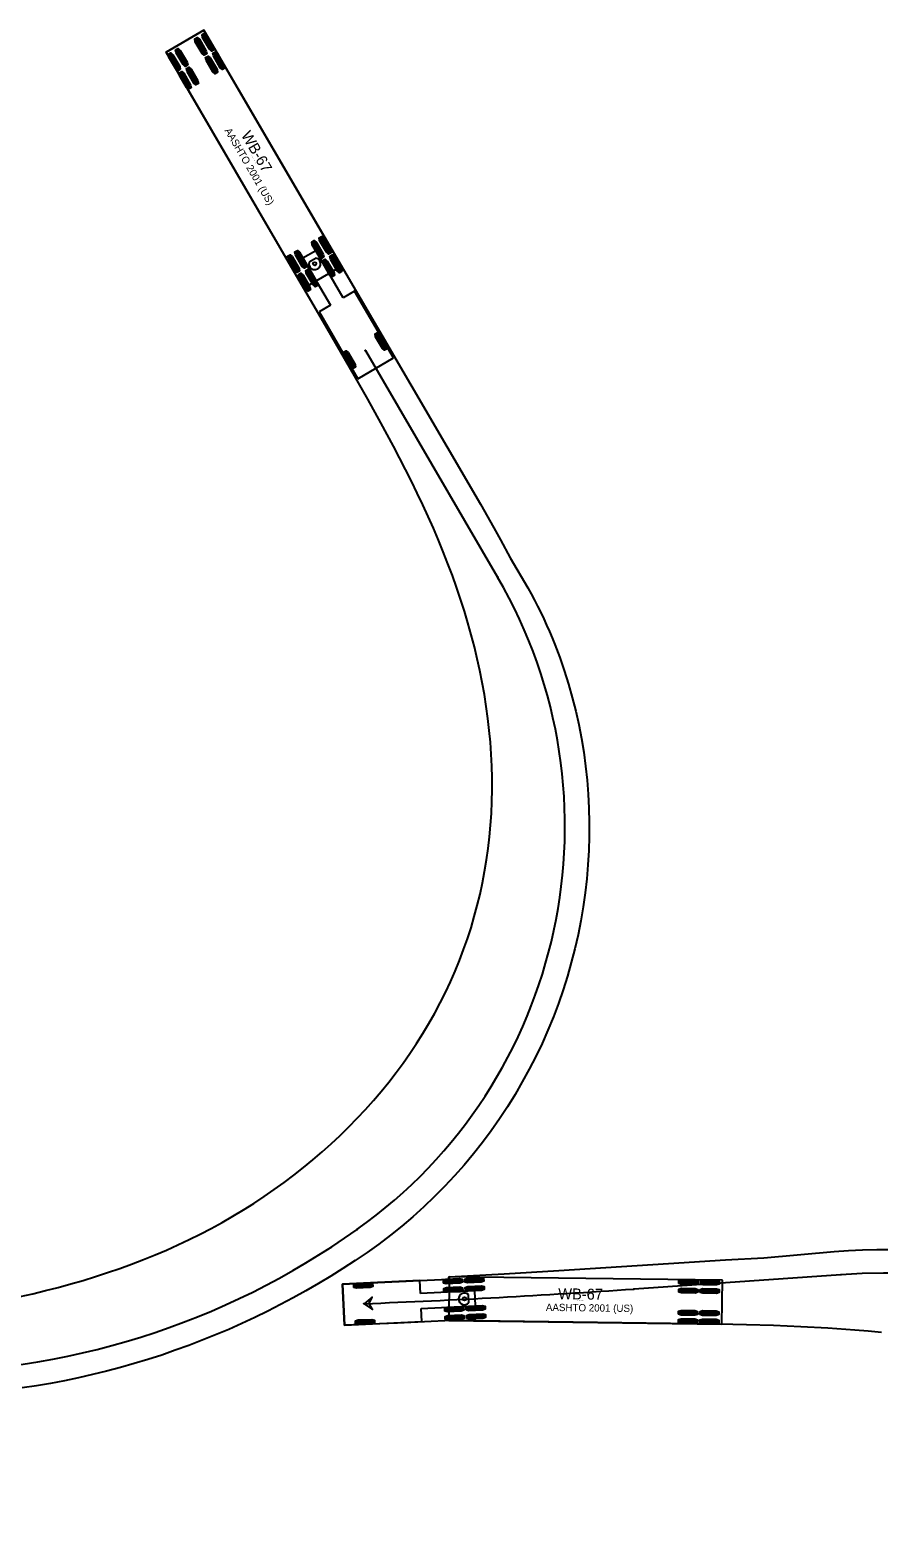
# Model space of a CAD drawing. Extents: x 1639988 to 1641860, y 841974 to 844187.
# Drawn here: x 1640795.3 to 1640960, y 842634.4 to 842927 of the extents above; entities that cross this region are included whole.
import ezdxf

# ---------------------------------------------------------------- set-up
doc = ezdxf.new("R2010")
doc.units = 0
doc.layers.add('Scratch_Level_1', color=7, linetype='Continuous')

msp = doc.modelspace()

# ---------------------------------------------------------------- linework, layer by layer
at = {"layer": 'Scratch_Level_1'}
for p, q in [((1640829.03, 842926.97), (1640821.69, 842922.69)), ((1640829.15, 842922.12), (1640827.31, 842925.29)), ((1640829.35, 842922.24), (1640827.5, 842925.4)), ((1640829.55, 842922.35), (1640827.7, 842925.52)), ((1640830.58, 842922.95), (1640828.73, 842926.12)), ((1640830.78, 842923.07), (1640828.93, 842926.24)), ((1640855.74, 842881.19), (1640829.03, 842926.97)), ((1640830.98, 842923.18), (1640829.13, 842926.35)), ((1640821.69, 842922.69), (1640848.4, 842876.91)), ((1640824.03, 842919.13), (1640822.18, 842922.3)), ((1640824.23, 842919.25), (1640822.38, 842922.41)), ((1640824.43, 842919.36), (1640822.58, 842922.53)), ((1640825.45, 842919.96), (1640823.61, 842923.13)), ((1640825.65, 842920.08), (1640823.8, 842923.24)), ((1640825.85, 842920.19), (1640824, 842923.36)), ((1640831.45, 842918.64), (1640829.6, 842921.8)), ((1640831.65, 842918.75), (1640829.8, 842921.92)), ((1640832.68, 842919.35), (1640830.83, 842922.52)), ((1640832.88, 842919.47), (1640831.03, 842922.64)), ((1640833.07, 842919.58), (1640831.23, 842922.75)), ((1640826.33, 842915.65), (1640824.48, 842918.81)), ((1640826.53, 842915.76), (1640824.68, 842918.93)), ((1640827.55, 842916.36), (1640825.71, 842919.53)), ((1640827.75, 842916.48), (1640825.9, 842919.65)), ((1640827.95, 842916.59), (1640826.1, 842919.76)), ((1640831.25, 842918.52), (1640829.41, 842921.69)), ((1640826.13, 842915.53), (1640824.28, 842918.7)), ((1640853.29, 842883.53), (1640851.45, 842886.69)), ((1640853.49, 842883.64), (1640851.64, 842886.81)), ((1640853.69, 842883.76), (1640851.84, 842886.93)), ((1640848.6, 842880.79), (1640846.75, 842883.96)), ((1640848.8, 842880.9), (1640846.95, 842884.07)), ((1640849, 842881.02), (1640847.15, 842884.19)), ((1640850.75, 842884.16), (1640848.27, 842882.72)), ((1640851.87, 842882.7), (1640850.02, 842885.86)), ((1640852.07, 842882.81), (1640850.22, 842885.98)), ((1640852.26, 842882.93), (1640850.42, 842886.09)), ((1640856.08, 842875.02), (1640850.75, 842884.16)), ((1640847.18, 842879.96), (1640845.33, 842883.12)), ((1640847.37, 842880.07), (1640845.53, 842883.24)), ((1640847.57, 842880.19), (1640845.72, 842883.36)), ((1640848.27, 842882.72), (1640853.6, 842873.58)), ((1640848.4, 842876.91), (1640855.74, 842881.19)), ((1640850.85, 842882.75), (1640849.45, 842881.93)), ((1640853.97, 842879.1), (1640852.12, 842882.26)), ((1640854.17, 842879.21), (1640852.32, 842882.38)), ((1640854.36, 842879.33), (1640852.52, 842882.5)), ((1640855.39, 842879.93), (1640853.55, 842883.1)), ((1640855.59, 842880.04), (1640853.74, 842883.21)), ((1640855.79, 842880.16), (1640853.94, 842883.33)), ((1640855.74, 842881.19), (1640855.74, 842881.19)), ((1640849.28, 842876.36), (1640847.43, 842879.53)), ((1640849.47, 842876.47), (1640847.63, 842879.64)), ((1640849.67, 842876.59), (1640847.82, 842879.76)), ((1640850.7, 842877.19), (1640848.85, 842880.36)), ((1640850.9, 842877.31), (1640849.05, 842880.47)), ((1640851.1, 842877.42), (1640849.25, 842880.59)), ((1640858.3, 842876.32), (1640856.08, 842875.02)), ((1640865.86, 842863.36), (1640858.3, 842876.32)), ((1640853.6, 842873.58), (1640851.39, 842872.28)), ((1640851.39, 842872.28), (1640858.95, 842859.33)), ((1640864.17, 842864.89), (1640862.32, 842868.05)), ((1640864.37, 842865), (1640862.52, 842868.17)), ((1640864.57, 842865.12), (1640862.72, 842868.28)), ((1640858.05, 842861.32), (1640856.21, 842864.48)), ((1640858.25, 842861.43), (1640856.4, 842864.6)), ((1640858.45, 842861.55), (1640856.6, 842864.71)), ((1640858.95, 842859.33), (1640865.86, 842863.36)), ((1640860.39, 842864.8), (1640886.04, 842820.84)), ((1640865.86, 842863.36), (1640865.86, 842863.36)), ((1640876.67, 842685.07), (1640876.56, 842676.57)), ((1640929.67, 842684.38), (1640876.67, 842685.07)), ((1640879.68, 842684.56), (1640883.34, 842684.74)), ((1640952.7, 842685.45), (1640912.54, 842682.68)), ((1640870.93, 842684.36), (1640855.95, 842683.63)), ((1640855.95, 842683.63), (1640856.34, 842675.64)), ((1640858.13, 842683.52), (1640861.79, 842683.67)), ((1640858.14, 842683.3), (1640861.8, 842683.44)), ((1640858.15, 842683.07), (1640861.81, 842683.21)), ((1640871.06, 842681.8), (1640870.93, 842684.36)), ((1640881.63, 842682.31), (1640871.06, 842681.8)), ((1640875.52, 842684.36), (1640879.18, 842684.53)), ((1640875.53, 842684.13), (1640879.19, 842684.31)), ((1640875.54, 842683.9), (1640879.2, 842684.08)), ((1640875.6, 842682.71), (1640879.26, 842682.89)), ((1640875.61, 842682.48), (1640879.27, 842682.66)), ((1640875.62, 842682.25), (1640879.28, 842682.43)), ((1640879.69, 842684.33), (1640883.36, 842684.51)), ((1640879.7, 842684.1), (1640883.37, 842684.28)), ((1640879.76, 842682.91), (1640883.42, 842683.09)), ((1640879.77, 842682.68), (1640883.44, 842682.86)), ((1640879.78, 842682.45), (1640883.45, 842682.63)), ((1640881.77, 842679.45), (1640881.63, 842682.31)), ((1640921.22, 842682.38), (1640924.89, 842682.33)), ((1640921.22, 842682.15), (1640924.89, 842682.11)), ((1640921.23, 842682.61), (1640924.89, 842682.56)), ((1640921.24, 842684.03), (1640924.91, 842683.98)), ((1640921.24, 842683.8), (1640924.91, 842683.76)), ((1640921.25, 842684.26), (1640924.91, 842684.21)), ((1640925.39, 842682.56), (1640929.06, 842682.51)), ((1640925.39, 842682.33), (1640929.06, 842682.28)), ((1640925.39, 842682.1), (1640929.05, 842682.05)), ((1640925.41, 842684.21), (1640929.08, 842684.16)), ((1640925.41, 842683.98), (1640929.08, 842683.93)), ((1640925.41, 842683.75), (1640929.07, 842683.7)), ((1640929.56, 842675.88), (1640929.67, 842684.38)), ((1640871.2, 842678.93), (1640881.77, 842679.45)), ((1640871.32, 842676.37), (1640871.2, 842678.93)), ((1640875.78, 842678.93), (1640879.45, 842679.11)), ((1640875.8, 842678.7), (1640879.46, 842678.88)), ((1640879.95, 842679.13), (1640883.61, 842679.31)), ((1640879.96, 842678.9), (1640883.62, 842679.08)), ((1640880.46, 842680.01), (1640880.38, 842681.63)), ((1640856.34, 842675.64), (1640871.32, 842676.37)), ((1640858.47, 842676.45), (1640862.13, 842676.6)), ((1640858.48, 842676.22), (1640862.14, 842676.37)), ((1640858.48, 842675.99), (1640862.15, 842676.14)), ((1640875.81, 842678.47), (1640879.47, 842678.65)), ((1640875.86, 842677.28), (1640879.53, 842677.46)), ((1640875.88, 842677.05), (1640879.54, 842677.23)), ((1640875.89, 842676.82), (1640879.55, 842677)), ((1640876.56, 842676.57), (1640929.56, 842675.88)), ((1640876.56, 842676.57), (1640876.56, 842676.57)), ((1640879.97, 842678.67), (1640883.63, 842678.85)), ((1640880.03, 842677.48), (1640883.69, 842677.66)), ((1640880.04, 842677.25), (1640883.7, 842677.43)), ((1640880.05, 842677.03), (1640883.71, 842677.2)), ((1640921.14, 842676.22), (1640924.81, 842676.17)), ((1640921.15, 842676.68), (1640924.82, 842676.63)), ((1640921.15, 842676.45), (1640924.81, 842676.4)), ((1640921.16, 842677.87), (1640924.83, 842677.82)), ((1640921.17, 842678.33), (1640924.84, 842678.28)), ((1640921.17, 842678.1), (1640924.83, 842678.05)), ((1640925.31, 842676.4), (1640928.98, 842676.35)), ((1640925.31, 842676.17), (1640928.98, 842676.12)), ((1640925.32, 842676.62), (1640928.98, 842676.58)), ((1640925.33, 842678.05), (1640929, 842678)), ((1640925.33, 842677.82), (1640929, 842677.77)), ((1640925.34, 842678.27), (1640929, 842678.23)), ((1640856.34, 842675.64), (1640856.34, 842675.64))]:
    msp.add_line(p, q, dxfattribs=at)
for points in [[(1640793.39, 842681.22), (1640795.87, 842681.78), (1640798.33, 842682.38), (1640800.78, 842683.01), (1640803.2, 842683.67), (1640805.61, 842684.37), (1640807.99, 842685.1), (1640810.36, 842685.87), (1640812.7, 842686.67), (1640815.01, 842687.51), (1640817.3, 842688.39), (1640819.57, 842689.3), (1640821.8, 842690.25), (1640824.01, 842691.25), (1640826.19, 842692.28), (1640828.34, 842693.34), (1640830.47, 842694.46), (1640832.57, 842695.61), (1640834.65, 842696.8), (1640836.7, 842698.03), (1640838.72, 842699.31), (1640840.72, 842700.62), (1640842.68, 842701.97), (1640844.61, 842703.36), (1640846.51, 842704.79), (1640848.37, 842706.26), (1640850.2, 842707.76), (1640852, 842709.3), (1640853.75, 842710.88), (1640855.47, 842712.49), (1640857.15, 842714.13), (1640858.79, 842715.81), (1640860.39, 842717.52), (1640861.95, 842719.26), (1640863.46, 842721.04), (1640864.92, 842722.84), (1640866.34, 842724.67), (1640867.72, 842726.53), (1640869.04, 842728.42), (1640870.32, 842730.33), (1640871.54, 842732.27), (1640872.72, 842734.23), (1640873.84, 842736.22), (1640874.91, 842738.22), (1640875.93, 842740.25), (1640876.89, 842742.3), (1640877.8, 842744.36), (1640878.65, 842746.45), (1640879.45, 842748.55), (1640880.2, 842750.67), (1640880.89, 842752.8), (1640881.53, 842754.95), (1640882.11, 842757.11), (1640882.64, 842759.3), (1640883.11, 842761.5), (1640883.53, 842763.72), (1640883.9, 842765.95), (1640884.22, 842768.19), (1640884.48, 842770.44), (1640884.69, 842772.71), (1640884.84, 842774.98), (1640884.94, 842777.27), (1640884.99, 842779.56), (1640884.98, 842781.86), (1640884.93, 842784.16), (1640884.82, 842786.47), (1640884.65, 842788.78), (1640884.44, 842791.09), (1640884.18, 842793.41), (1640883.86, 842795.73), (1640883.5, 842798.04), (1640883.08, 842800.36), (1640882.62, 842802.68), (1640882.11, 842805), (1640881.55, 842807.31), (1640880.95, 842809.62), (1640880.3, 842811.93), (1640879.61, 842814.24), (1640878.87, 842816.55), (1640878.09, 842818.85), (1640877.27, 842821.15), (1640876.4, 842823.44), (1640875.5, 842825.73), (1640874.56, 842828.02), (1640873.59, 842830.31), (1640872.57, 842832.59), (1640871.53, 842834.87), (1640870.45, 842837.15), (1640869.34, 842839.43), (1640868.2, 842841.7), (1640867.04, 842843.98), (1640865.85, 842846.25), (1640863.4, 842850.8), (1640860.87, 842855.35), (1640858.28, 842859.91), (1640852.97, 842869.08), (1640821.69, 842922.69), (1640829.03, 842926.97), (1640829.1, 842926.84), (1640829.1, 842926.84)], [(1640829.1, 842926.84), (1640882.7, 842834.99), (1640885.33, 842830.39), (1640886.62, 842828.07), (1640888.5, 842824.56), (1640891.89, 842818.74), (1640892.55, 842817.56), (1640893.19, 842816.37), (1640893.81, 842815.17), (1640894.42, 842813.96), (1640895, 842812.74), (1640895.56, 842811.51), (1640896.11, 842810.27), (1640896.64, 842809.02), (1640897.14, 842807.77), (1640898.11, 842805.24), (1640898.99, 842802.68), (1640899.8, 842800.09), (1640900.54, 842797.48), (1640901.21, 842794.85), (1640901.8, 842792.2), (1640902.31, 842789.53), (1640902.76, 842786.84), (1640903.12, 842784.14), (1640903.42, 842781.42), (1640903.63, 842778.7), (1640903.78, 842775.97), (1640903.84, 842773.23), (1640903.83, 842770.49), (1640903.75, 842767.75), (1640903.59, 842765.01), (1640903.35, 842762.28), (1640903.04, 842759.55), (1640902.66, 842756.82), (1640902.2, 842754.11), (1640901.66, 842751.4), (1640901.05, 842748.71), (1640900.36, 842746.04), (1640899.6, 842743.38), (1640898.77, 842740.73), (1640897.86, 842738.11), (1640896.87, 842735.5), (1640895.82, 842732.92), (1640894.68, 842730.36), (1640893.48, 842727.83), (1640892.2, 842725.33), (1640890.85, 842722.87), (1640889.44, 842720.44), (1640887.95, 842718.04), (1640886.4, 842715.69), (1640884.78, 842713.39), (1640883.09, 842711.12), (1640881.34, 842708.91), (1640879.53, 842706.74), (1640877.66, 842704.63), (1640875.73, 842702.56), (1640873.74, 842700.56), (1640871.7, 842698.61), (1640869.61, 842696.71), (1640867.46, 842694.88), (1640865.26, 842693.11), (1640863.02, 842691.4), (1640860.73, 842689.76), (1640858.4, 842688.19), (1640856.04, 842686.66), (1640853.66, 842685.17), (1640851.26, 842683.73), (1640848.83, 842682.33), (1640846.39, 842680.97), (1640843.92, 842679.66), (1640841.43, 842678.4), (1640838.93, 842677.17), (1640836.4, 842676), (1640833.86, 842674.86), (1640831.3, 842673.78), (1640828.71, 842672.73), (1640826.11, 842671.74), (1640823.49, 842670.79), (1640820.85, 842669.88), (1640818.19, 842669.02), (1640815.52, 842668.21), (1640812.84, 842667.45), (1640810.14, 842666.74), (1640807.44, 842666.08), (1640804.72, 842665.46), (1640802, 842664.89), (1640799.27, 842664.38), (1640796.53, 842663.91), (1640793.78, 842663.49)], [(1640960.57, 842674.28), (1640957.97, 842674.51), (1640955.36, 842674.72), (1640950.13, 842675.08), (1640944.88, 842675.36), (1640939.61, 842675.59), (1640934.33, 842675.76), (1640929.03, 842675.88), (1640877.1, 842676.56), (1640866.61, 842676.06), (1640856.34, 842675.64), (1640855.95, 842683.63), (1640876.52, 842684.62), (1640876.67, 842685.07), (1640887.32, 842685.65), (1640897.96, 842686.29), (1640919.23, 842687.66), (1640930.28, 842688.35), (1640937.73, 842688.76), (1640951.4, 842689.96), (1640954.15, 842690.14), (1640956.9, 842690.27), (1640959.66, 842690.34), (1640962.42, 842690.36)], [(1640860.14, 842679.83), (1640861.77, 842678.68), (1640861.14, 842679.87), (1640861.68, 842681.11), (1640860.14, 842679.83)]]:
    msp.add_lwpolyline(points, dxfattribs=at)
for points in [[(1640829.6, 842922.38), (1640829.1, 842922.09), (1640828.7, 842922.45), (1640827.37, 842924.73), (1640827.26, 842925.26), (1640827.75, 842925.55), (1640828.16, 842925.19), (1640829.49, 842922.91)], [(1640831.02, 842923.21), (1640830.53, 842922.92), (1640830.12, 842923.28), (1640828.79, 842925.56), (1640828.68, 842926.09), (1640829.18, 842926.38), (1640829.58, 842926.02), (1640830.91, 842923.74)], [(1640824.47, 842919.39), (1640823.98, 842919.1), (1640823.57, 842919.46), (1640822.24, 842921.74), (1640822.13, 842922.27), (1640822.63, 842922.56), (1640823.03, 842922.2), (1640824.36, 842919.92)], [(1640825.9, 842920.22), (1640825.41, 842919.93), (1640825, 842920.29), (1640823.67, 842922.57), (1640823.56, 842923.1), (1640824.05, 842923.39), (1640824.46, 842923.03), (1640825.79, 842920.75)], [(1640831.7, 842918.78), (1640831.2, 842918.49), (1640830.8, 842918.85), (1640829.47, 842921.13), (1640829.36, 842921.66), (1640829.85, 842921.95), (1640830.26, 842921.59), (1640831.59, 842919.31)], [(1640833.12, 842919.61), (1640832.63, 842919.33), (1640832.22, 842919.68), (1640830.89, 842921.96), (1640830.78, 842922.49), (1640831.28, 842922.78), (1640831.68, 842922.42), (1640833.01, 842920.14)], [(1640826.57, 842915.79), (1640826.08, 842915.5), (1640825.67, 842915.86), (1640824.34, 842918.14), (1640824.23, 842918.67), (1640824.73, 842918.96), (1640825.13, 842918.6), (1640826.46, 842916.32)], [(1640828, 842916.62), (1640827.51, 842916.33), (1640827.1, 842916.69), (1640825.77, 842918.97), (1640825.66, 842919.5), (1640826.15, 842919.79), (1640826.56, 842919.43), (1640827.89, 842917.15)], [(1640853.74, 842883.79), (1640853.25, 842883.5), (1640852.84, 842883.86), (1640851.51, 842886.14), (1640851.4, 842886.67), (1640851.89, 842886.95), (1640852.3, 842886.6), (1640853.63, 842884.32)], [(1640849.05, 842881.05), (1640848.55, 842880.76), (1640848.14, 842881.12), (1640846.81, 842883.4), (1640846.7, 842883.93), (1640847.2, 842884.22), (1640847.61, 842883.86), (1640848.94, 842881.58)], [(1640852.31, 842882.96), (1640851.82, 842882.67), (1640851.41, 842883.02), (1640850.08, 842885.3), (1640849.97, 842885.83), (1640850.47, 842886.12), (1640850.87, 842885.77), (1640852.2, 842883.49)], [(1640847.62, 842880.22), (1640847.13, 842879.93), (1640846.72, 842880.29), (1640845.39, 842882.57), (1640845.28, 842883.1), (1640845.77, 842883.38), (1640846.18, 842883.03), (1640847.51, 842880.75)], [(1640854.41, 842879.36), (1640853.92, 842879.07), (1640853.51, 842879.42), (1640852.18, 842881.71), (1640852.07, 842882.24), (1640852.57, 842882.52), (1640852.97, 842882.17), (1640854.3, 842879.89)], [(1640855.84, 842880.19), (1640855.35, 842879.9), (1640854.94, 842880.26), (1640853.61, 842882.54), (1640853.5, 842883.07), (1640853.99, 842883.36), (1640854.4, 842883), (1640855.73, 842880.72)], [(1640849.72, 842876.62), (1640849.23, 842876.33), (1640848.82, 842876.69), (1640847.49, 842878.97), (1640847.38, 842879.5), (1640847.87, 842879.79), (1640848.28, 842879.43), (1640849.61, 842877.15)], [(1640851.15, 842877.45), (1640850.65, 842877.16), (1640850.24, 842877.52), (1640848.91, 842879.8), (1640848.8, 842880.33), (1640849.3, 842880.62), (1640849.71, 842880.26), (1640851.04, 842877.98)], [(1640864.62, 842865.15), (1640864.12, 842864.86), (1640863.72, 842865.21), (1640862.38, 842867.49), (1640862.27, 842868.02), (1640862.77, 842868.31), (1640863.18, 842867.96), (1640864.51, 842865.68)], [(1640858.5, 842861.58), (1640858, 842861.29), (1640857.6, 842861.64), (1640856.27, 842863.92), (1640856.16, 842864.45), (1640856.65, 842864.74), (1640857.06, 842864.39), (1640858.39, 842862.11)], [(1640875.55, 842683.84), (1640875.52, 842684.41), (1640876.02, 842684.61), (1640878.66, 842684.74), (1640879.18, 842684.59), (1640879.21, 842684.02), (1640878.7, 842683.82), (1640876.07, 842683.69)], [(1640879.71, 842684.04), (1640879.68, 842684.62), (1640880.18, 842684.81), (1640882.82, 842684.94), (1640883.34, 842684.79), (1640883.37, 842684.22), (1640882.86, 842684.03), (1640880.23, 842683.9)], [(1640858.15, 842683.01), (1640858.13, 842683.58), (1640858.63, 842683.77), (1640861.27, 842683.88), (1640861.79, 842683.73), (1640861.81, 842683.16), (1640861.31, 842682.96), (1640858.67, 842682.86)], [(1640875.63, 842682.19), (1640875.6, 842682.76), (1640876.1, 842682.96), (1640878.74, 842683.09), (1640879.26, 842682.94), (1640879.29, 842682.37), (1640878.78, 842682.17), (1640876.15, 842682.05)], [(1640879.79, 842682.4), (1640879.76, 842682.97), (1640880.26, 842683.16), (1640882.9, 842683.29), (1640883.42, 842683.15), (1640883.45, 842682.57), (1640882.95, 842682.38), (1640880.31, 842682.25)], [(1640921.22, 842682.1), (1640921.23, 842682.67), (1640921.74, 842682.83), (1640924.38, 842682.8), (1640924.89, 842682.62), (1640924.89, 842682.05), (1640924.37, 842681.88), (1640921.73, 842681.92)], [(1640921.24, 842683.75), (1640921.25, 842684.32), (1640921.76, 842684.48), (1640924.4, 842684.45), (1640924.91, 842684.27), (1640924.91, 842683.7), (1640924.39, 842683.53), (1640921.75, 842683.57)], [(1640925.39, 842682.04), (1640925.39, 842682.61), (1640925.91, 842682.78), (1640928.55, 842682.75), (1640929.06, 842682.57), (1640929.05, 842681.99), (1640928.54, 842681.83), (1640925.9, 842681.86)], [(1640925.41, 842683.69), (1640925.41, 842684.26), (1640925.93, 842684.43), (1640928.57, 842684.4), (1640929.08, 842684.22), (1640929.07, 842683.64), (1640928.56, 842683.48), (1640925.92, 842683.51)], [(1640860.14, 842679.83), (1640861.77, 842678.68), (1640861.14, 842679.87), (1640861.68, 842681.11)], [(1640875.81, 842678.41), (1640875.78, 842678.99), (1640876.29, 842679.18), (1640878.92, 842679.31), (1640879.44, 842679.16), (1640879.47, 842678.59), (1640878.97, 842678.4), (1640876.33, 842678.27)], [(1640879.97, 842678.62), (1640879.94, 842679.19), (1640880.45, 842679.39), (1640883.08, 842679.51), (1640883.61, 842679.37), (1640883.63, 842678.8), (1640883.13, 842678.6), (1640880.49, 842678.47)], [(1640858.49, 842675.93), (1640858.46, 842676.51), (1640858.97, 842676.7), (1640861.61, 842676.8), (1640862.13, 842676.65), (1640862.15, 842676.08), (1640861.64, 842675.89), (1640859.01, 842675.78)], [(1640875.89, 842676.77), (1640875.86, 842677.34), (1640876.37, 842677.53), (1640879, 842677.66), (1640879.52, 842677.52), (1640879.55, 842676.94), (1640879.05, 842676.75), (1640876.41, 842676.62)], [(1640880.05, 842676.97), (1640880.02, 842677.54), (1640880.53, 842677.74), (1640883.16, 842677.87), (1640883.69, 842677.72), (1640883.71, 842677.15), (1640883.21, 842676.95), (1640880.57, 842676.82)], [(1640921.14, 842676.16), (1640921.15, 842676.74), (1640921.67, 842676.9), (1640924.31, 842676.87), (1640924.82, 842676.69), (1640924.81, 842676.12), (1640924.29, 842675.95), (1640921.65, 842675.98)], [(1640921.16, 842677.81), (1640921.17, 842678.39), (1640921.69, 842678.55), (1640924.33, 842678.52), (1640924.84, 842678.34), (1640924.83, 842677.77), (1640924.31, 842677.6), (1640921.67, 842677.63)], [(1640925.31, 842676.11), (1640925.32, 842676.68), (1640925.83, 842676.85), (1640928.47, 842676.81), (1640928.98, 842676.63), (1640928.98, 842676.06), (1640928.46, 842675.9), (1640925.82, 842675.93)], [(1640925.33, 842677.76), (1640925.34, 842678.33), (1640925.85, 842678.5), (1640928.49, 842678.46), (1640929, 842678.28), (1640929, 842677.71), (1640928.48, 842677.55), (1640925.84, 842677.58)]]:
    msp.add_lwpolyline(points, close=True, dxfattribs=at)
for centre, radius in [((1640850.56, 842881.64), 0.34), ((1640860.39, 842864.8), 0.0417), ((1640886.04, 842820.84), 0.0417), ((1640886.04, 842820.84), 0.0417), ((1640858.76, 842694.22), 0.0417), ((1640858.76, 842694.22), 0.0417), ((1640952.7, 842685.45), 0.0417), ((1640952.7, 842685.45), 0.0417), ((1640912.54, 842682.68), 0.0417), ((1640912.54, 842682.68), 0.0417), ((1640860.14, 842679.83), 0.0417), ((1640879.62, 842680.78), 0.34)]:
    msp.add_circle(centre, radius, dxfattribs=at)
for centre, radius, start, end in [((1640850.56, 842881.64), 1.14, 165.2635, 75.2635), ((1640803.12, 842772.45), 96, 305.4186, 30.2635), ((1640771.83, 842816.46), 150, 269.456, 305.4186), ((1640961.78, 842553.77), 132, 37.6529, 93.9449), ((1640787.74, 844492.39), 1814, 272.28734, 273.94492), ((1640879.62, 842680.78), 1.14, 47.7887, 317.7887)]:
    msp.add_arc(centre, radius, start, end, dxfattribs=at)

# ---------------------------------------------------------------- texts
for s, height, rotation, p in [('AASHTO 2001 (US)', 1.4167, 300.2635, (1640833.01, 842907.49)), ('WB-67', 2.125, 300.2635, (1640836.19, 842906.61)), ('(c) 2019 Transoft Solutions, Inc. All rights reserved.', 0.085, 300.2635, (1640837.81, 842903.41)), ('WB-67', 2.125, 359.2571, (1640897.8, 842680.71)), ('AASHTO 2001 (US)', 1.4167, 359.2571, (1640895.42, 842678.44)), ('(c) 2019 Transoft Solutions, Inc. All rights reserved.', 0.085, 359.2571, (1640901.38, 842680.46))]:
    msp.add_text(s, height=height, rotation=rotation, dxfattribs=at).set_placement(p)

doc.saveas('drawing.dxf')
